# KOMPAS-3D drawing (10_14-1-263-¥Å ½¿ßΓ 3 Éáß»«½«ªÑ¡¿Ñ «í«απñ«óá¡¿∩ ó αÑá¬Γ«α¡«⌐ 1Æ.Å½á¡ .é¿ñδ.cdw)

Views: Вид 1, Вид 2, Вид 3
Referenced files in C:\Program Files\ASCON\KOMPAS-3D V10\Sys\: Graphic.lcs
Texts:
  Стена
  Металлич. перекрытия
  Сэндвич-панели 100
  Блоки фундаментные 400
  Сэндвич-панели 150
  Текст на чертеже
  Размерные надписи
  Шероховатость
  Линия-выноска #1
  Линия-выноска #2
  Линия-выноска #3
  Отклонения формы и база
  Заголовок таблицы
  Ячейка таблицы
  Стрелка вида
  Обозначение изменения
  Фигурная скобка
  Номер узла
  Марка координационной оси
  VRCB
  Выносная надпись
  Обозначение узла
  Марка/позиционное обозначение с линией-выноской
  Марка/позиционное обозначение на линии
  Марка/позиционное обозначение без линии-выноски
  Normal
  txt
  Body Text
  heading 1
  Знак Знак Знак Знак Знак Знак
  Verdana
  Лит-Масса-Масштаб
  Материал-Предприятие
  MS Sans Serif
  Simplex
  Txt
  Title Specification
  Body Specification ( left align )
  Body Specificaton ( centered )
  Без имени
  Additional DXF text style 0
  Обычный
  Термин
  Список определений
  Адрес
  Цитаты
  Форматированный
  Courier New
  Z-конец формы
  Z-начало формы
  ТекстШаг1
  Денис
  heading 2
  AGOpus
  footer
  Title
  ООббыыччнныыйй
  Definition Term
  Definition List
  Address
  Blockquote
  Preformatted
  z-Bottom of Form
  z-Top of Form
  TXT
  header
  heading 8
  heading 3
  heading 6
  heading 7
  russ
  ТТееррммиинн
  ССппииссоокк ооппррееддееллеенниийй
  ААддрреесс
  ЦЦииттааттыы
  ФФооррммааттиирроовваанннныыйй
  Z-ккооннеецц ффооррммыы
  Z-ннааччааллоо ффооррммыы
  Абзац Знак
  heading 4
  heading 5
  heading 9
  GOST 2.304 type A
  rustxt
  цепи
  ссылки
  Маркировка
  Подпись в квадратике
  табл
  ЗОНА_привяз
  маркировка
  ГОСТ_МНЕ
  ESK - Обозначение
  текст переноса
  Тексты. 3,2
  Body Text 3
  клеммы, контакты
  тексты табл
  ISOCP
  HeliosLight
  Pa3
  Pa1
  Шрифт 2.5
  Заголовки
  RUSTXT
  NormalParagraphStyle
  Три с половиной
  style2
  Table Contents
  Table Heading
  Tahoma
  FR5
  Текст 3,5
  Subtitle
  romanc
  eskd1
  Pa15
  Pa18
  CNBNDG+TimesNewRoman
  Аппараты
  подписи
  Состав чартежа
  ячейка табл.
  Ссылки
  Пояснения
  Клеммник текст
  CM12
  romans
  gif
  Пояснения 2
  текст табл
  ISOCPEUR
  CC С?т?и?л?ь? П?о? ц?е?н?т?р?у?
  Courier New Cyr
  ROMANS
  SIMPLEX
  Обычный (веб)
  .07 RGB_0_0_0 i0b0u0
  Body Text Indent 3
  Основной текст с отступом 3
  надписи
  экспликация
  Здание
  Оси
  Поз.
  Кол.
  ед., кг
  Приме-
  чание
  Реактор токоограничивающий 6 кВ
  РТСТ 6-3200-0,35 УХЛ3 (компл. 3 фазы)
  Опорный изолятор 10 кВ
  ИО-10-3,75-II-У3
  Проходной изолятор 10 кВ
  ИПУ-10/3150-12,5-УХЛ1
  Шина алюминиевая 2хAl-100 10
  Шкаф собственных нужд
  реакторной 1Т
  см. п.п.14
  см. п.п.4
  Перечень оборудования
  Примечания:
  1. Предусмотреть односкатную кровлю, со скатом в сторону оси А.
  2. Предусмотреть возможность демонтажа и повторной установки крыши и стены по оси 3 для
  ремонтных работ с реакторами.
  3. Предусмотреть несущую конструкцию  пола.
  4. В комплект поставки включить:
  - проходные изоляторы в количестве 6 шт.,
  - опорные изоляторы, жесткую ошиновку и арматуру для её крепления к изоляторам в количестве,
  достаточном для выполнения трассы разводки жесткой ошиновки по стенам и подключения
  реакторов,в соответствии с планом здания реакторной.
  - оборудование для организации силовой и осветительной сети в соответствии с 10/14-1-263-ЭП
  лист 5.
  - шкаф собственных нужд реакторной см. 10/14-1-263 лист 5.
  - крылечную металлическую лестницу.
  5. Выполнить разводку жесткой ошиновки по стенам, установку проходных изоляторов и крепление к
  ним ошиновки. Трасса разводки жесткой ошиновки должна удовлетворять требованиям ПУЭ 7 издание.
  Междуфазные расстояния принять не менее 500 мм ,длину пролета между опорными изоляторами
  принять не более 800 мм.
  6. Предусмотреть входную металлическую дверь-2100х800 мм.
  7. Для предотвращения прикосновения к неизолированным токоведущим частям в здании реакторной
  предусмотреть съемное сетчатое ограждение высотой 1900 мм.
  8. На полу предусмотреть опалубку для заливки бетонной подушки.
  9. В полу под шкафом собственных нужд реакторной предусмотреть технологическое отверстие
  диаметром 60 мм.
  10. В местах подвеса  натяжных гирлянд предусмотреть усиление конструкции, с закладной деталью и
  узлом крепления типа КГП 7-1.
  11. Установку проходных изоляторов выполнить в соответствии с требованиями СНиП 3.05.06-85.
  12. Предусмотреть естественную приточно-вытяжную и механическую вытяжную вентиляцию (см.
  10/14-1-263-ЭП, лист 5). Наклон жалюзей вентиляционных решеток см. узел 2.
  13. Освещение здания выполнить в соответствии с 10/14-1-263-ЭП, лист 5.
  14. Монтаж реакторов на бетонную подушку осуществляется подрядной организацией на месте
  установки реакторной.
  15. Пунктирной линией показано оборудование, не входящее в поставку завода.
  Сетчатое ограждение
  см п.п. 7
  Свайный фундамент
  см. 10/14-1-113-КС лист 11
  Бетонная подушка
  см п.п. 8
  вентиляционная
  решетка 1500х1000
  Узел 1
  (увеличено)
  см. п.п.10
  Узел 2
  Жалюзи вентиляционной
  решетки
  POLYLINE_STYLE_0.73_RGB_0_0_0
  DIVIDE_RGB_0_0_0_SC_1_THICK_0.18
  DASHDOT1_RGB_0_0_0_SC_1_THICK_0.18
  осн 2
  K5LT_BASIC_RGB_0_0_255_THICK_0.3
  K5LT_AXLED_RGB_255_255_0_SC_1_THICK_0.09
  K5LT_REINFORCED_RGB_255_0_0_THICK_0.6
  POLYLINE_STYLE_0.30_RGB_0_0_255
  K5LT_THIN_RGB_0_0_0_THICK_0.09
  K5LT_THIN_INCLUDED_TO_HATCHING_RGB_0_0_0_THICK_0.09
  K5LT32769_RGB_0_0_0_THICK_0.09
  K5LT_THIN_RGB_0_0_0_THICK_0.13
  ACAD_ISO04W100_RGB_255_0_0_SC_1_THICK_0.13
  Стили документа
  Бетон
  Бетон 0
  Бетон 1
  Бетон 2
  Бетон 3
  Расположение оборудования в
  реакторной 1Т. План. Виды
  Н.контр.
  Разраб.
  Скахин
  Реконструкция ПС 110 кВ Опорная
  (замена трансформаторов 16МВА на 40МВА)
  Ведомость эскизного проекта
Dimensions and other numbers on the sheet: 10/14-1-263-ЭП; 5; 0; 7; 2,5; 3.5; 2.5; 1,8; 2,5 (контакты, клеммы); 2.5 курсив; 2,5_3; 3,2 (надписи); 3,5_01; 2,5_01; 3,5_tabl; 5_заголовок; 2,3_; 3,2_; 3,2_зона не привяз; 2,5 грязносинь; 5,0_белый_подчёркнутый; 3,2; 3.2 фиол; 3,5; 3,2 элементы; 3,2 линия; 3,2 таблица; 3.2 маркировка; 2.5_Э5_надписи; 2.5_Э5_ссылки; 2.5_кабель; 3.2; 2.5 надписи; 3,2 (Зоны); 3 и 5; 3.2 (текст); 0 i0b0u0; 1; 2; 3; 4; 10/14-1-263-ЭП лист 5; 6; 3690; 500; 1600; 750; 1430; 1015; 800; 4500; 4200; 300; 1750; 6900; 600; 1450; 1100; 1445; 1380; 1460; 2090; 6250; 430; 1135; 985; 200; 1270; 100; 1000; 835; 1030; 1230; 1680; 77; 11.12; 10/14-1-ИОС7.1-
